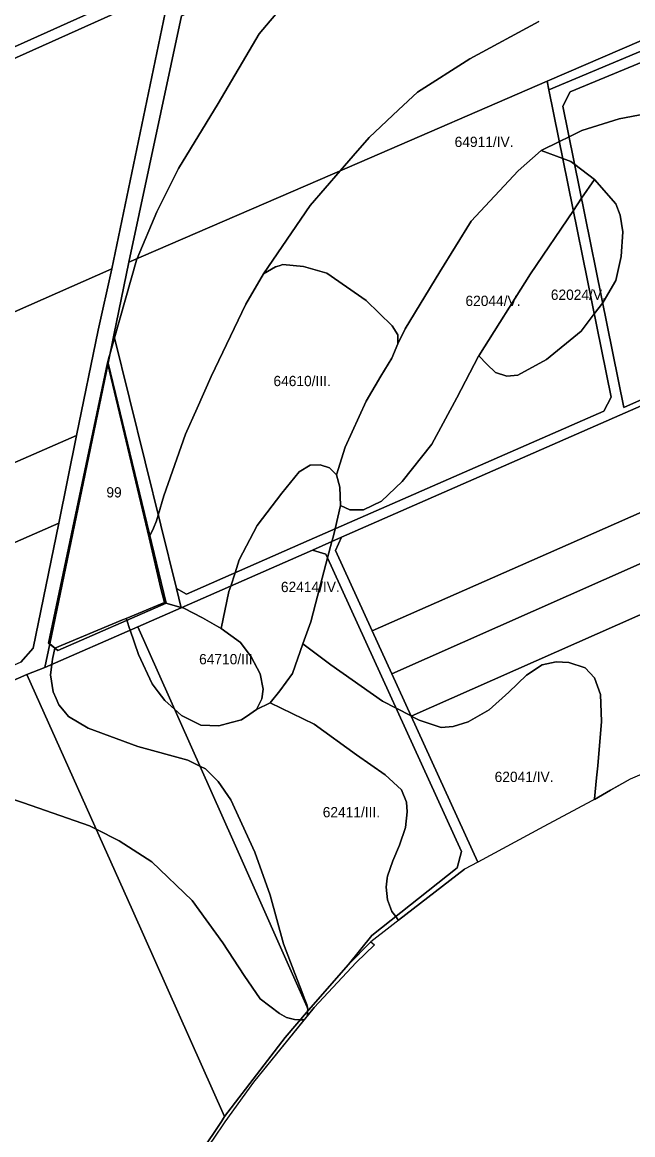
# Model space of a CAD drawing. Extents: x -522079 to -518833, y -1142400 to -1139961.
# Drawn here: x -520891 to -520594, y -1142050 to -1141508 of the extents above; entities that cross this region are included whole.
import ezdxf

# ---------------------------------------------------------------- set-up
doc = ezdxf.new("R2010")
doc.units = 0
for name, color, linetype in [('95560013', 7, 'Continuous'), ('95620013', 7, 'Continuous'), ('95640013', 7, 'Continuous'), ('95660013', 7, 'Continuous')]:
    doc.layers.add(name, color=color, linetype=linetype)

msp = doc.modelspace()

# ---------------------------------------------------------------- linework, layer by layer
at = {"layer": '95560013'}
for points in [[(-520659.49, -1141438.15), (-520585.72, -1141406.64), (-520580.93, -1141457.51), (-520574.39, -1141497.17), (-520572, -1141509.22), (-520635.55, -1141536.73), (-520726.9, -1141576.27), (-520838.97, -1141624.77), (-520813.35, -1141504.9)], [(-520821.3, -1141482.16), (-520824.28, -1141488.21), (-520974.97, -1141555.99), (-521072.78, -1141598.79), (-521078.78, -1141596.05), (-521084.21, -1141576.91), (-520955.18, -1141519.6), (-520826.14, -1141462.3)], [(-520819.82, -1141495.44), (-520822.47, -1141493.04), (-520972.97, -1141560.63), (-521070.28, -1141603.2), (-521076.03, -1141605.72), (-521077.42, -1141600.82), (-521072.78, -1141598.79), (-520974.97, -1141555.99), (-520824.28, -1141488.21), (-520821.3, -1141482.16)], [(-520822.47, -1141493.04), (-520819.82, -1141495.44), (-520847.36, -1141628.04), (-520954.68, -1141675.43), (-521044.98, -1141715.3), (-521058.67, -1141667), (-521074.66, -1141610.52), (-521070.28, -1141603.2), (-520972.97, -1141560.63)], [(-520572, -1141509.22), (-520571.03, -1141514.08), (-520634.69, -1141540.99), (-520635.55, -1141536.73)], [(-520624.36, -1141541.82), (-520627.91, -1141548.79), (-520598.21, -1141695.54), (-520529.1, -1141664.77), (-520528.04, -1141667.68), (-520597.66, -1141698.25), (-520735.52, -1141758.79), (-520749.7, -1141765.02), (-520813.61, -1141793.09), (-520815.91, -1141783.74), (-520811.05, -1141786.45), (-520751.28, -1141760.21), (-520608.03, -1141697.31), (-520604.47, -1141690.49), (-520634.69, -1141540.99), (-520571.03, -1141514.08), (-520569.98, -1141519.36)], [(-520627.91, -1141548.79), (-520624.36, -1141541.82), (-520569.98, -1141519.36), (-520566.58, -1141536.47), (-520557.06, -1141576.08), (-520545.85, -1141614.67), (-520536.49, -1141644.52), (-520529.1, -1141664.77), (-520598.21, -1141695.54)], [(-520608.03, -1141697.31), (-520751.28, -1141760.21), (-520811.05, -1141786.45), (-520815.91, -1141783.74), (-520846.32, -1141660.34), (-520838.97, -1141624.77), (-520726.9, -1141576.27), (-520635.55, -1141536.73), (-520634.69, -1141540.99), (-520604.47, -1141690.49)], [(-521044.98, -1141715.3), (-520954.68, -1141675.43), (-520847.36, -1141628.04), (-520854, -1141657.98), (-520864.49, -1141709.14), (-521026.62, -1141780.12)], [(-520738.58, -1141765.16), (-520735.52, -1141758.79), (-520597.66, -1141698.25), (-520528.04, -1141667.68), (-520522.71, -1141682.28), (-520510.4, -1141711.55), (-520625.27, -1141762.24), (-520720.69, -1141804.35)], [(-521026.62, -1141780.12), (-520864.49, -1141709.14), (-520873.01, -1141751.95), (-521016.76, -1141814.92)], [(-520501.37, -1141732.13), (-520539.21, -1141748.91), (-520711.18, -1141825.18), (-520720.69, -1141804.35), (-520625.27, -1141762.24), (-520510.4, -1141711.55), (-520506.95, -1141719.75)], [(-520711.18, -1141825.18), (-520539.21, -1141748.91), (-520501.37, -1141732.13), (-520491.98, -1141752.99), (-520530.72, -1141770.15), (-520701.74, -1141845.88)], [(-520873.01, -1141751.95), (-520885.53, -1141812.75), (-520891.63, -1141819.53), (-520930.02, -1141836.55), (-520997.06, -1141866.15), (-521003.04, -1141863.38), (-521016.76, -1141814.92)], [(-520701.74, -1141845.88), (-520530.72, -1141770.15), (-520491.98, -1141752.99), (-520490.19, -1141756.96), (-520458.87, -1141815.72), (-520465.55, -1141819.35), (-520477.66, -1141826.82), (-520503.7, -1141838.29), (-520515.18, -1141841.56), (-520545.58, -1141853.73), (-520565.76, -1141863.93), (-520595.23, -1141876.48), (-520613.84, -1141887.11), (-520637.23, -1141899.54), (-520669.31, -1141916.94)], [(-520720.87, -1141952.69), (-520679.41, -1141919.74), (-520677.16, -1141911.77), (-520743.17, -1141766.98), (-520749.7, -1141765.02), (-520735.52, -1141758.79), (-520738.58, -1141765.16), (-520720.69, -1141804.35), (-520711.18, -1141825.18), (-520701.74, -1141845.88), (-520669.31, -1141916.94), (-520675.72, -1141920.42), (-520721.33, -1141955.66), (-520732.26, -1141966.77)], [(-520788.5, -1141906.13), (-520834.71, -1141802.36), (-520813.61, -1141793.09), (-520749.7, -1141765.02), (-520743.17, -1141766.98), (-520677.16, -1141911.77), (-520679.41, -1141919.74), (-520720.87, -1141952.69), (-520732.26, -1141966.77), (-520751.6, -1141988.95)], [(-520837.29, -1141940.33), (-520888.63, -1141825.55), (-520879.93, -1141822.22), (-520834.71, -1141802.36), (-520788.5, -1141906.13), (-520751.6, -1141988.95), (-520762.92, -1142002.26), (-520792.44, -1142040.74)], [(-520997.93, -1141879.1), (-520995.39, -1141872.52), (-520888.63, -1141825.55), (-520837.29, -1141940.33), (-520792.44, -1142040.74), (-520794.02, -1142043.2), (-520832.63, -1142100.89), (-520865.14, -1142158.06), (-520874.16, -1142159.29), (-520905.36, -1142088.65), (-520939.85, -1142010.61), (-520967.25, -1141948.55)], [(-520865.14, -1142158.06), (-520832.63, -1142100.89), (-520794.02, -1142043.2), (-520792.44, -1142040.74), (-520762.92, -1142002.26), (-520751.6, -1141988.95), (-520732.26, -1141966.77), (-520721.33, -1141955.66), (-520719.53, -1141957.2), (-520728.5, -1141965.87), (-520748.85, -1141987.64), (-520778.35, -1142023.99), (-520792.36, -1142043.35), (-520798.04, -1142051.82), (-520812.28, -1142071.49), (-520845.48, -1142126.69), (-520864.2, -1142161.29), (-520868.95, -1142171.08), (-520870.13, -1142168.42)]]:
    msp.add_lwpolyline(points, close=True, dxfattribs=at)
at = {"layer": '95620013'}
msp.add_lwpolyline([(-520873.57, -1141813.91), (-520877.47, -1141810.66), (-520849.15, -1141674.02), (-520820.88, -1141790.77)], close=True, dxfattribs=at)
at = {"layer": '95640013'}
for points in [[(-520891.63, -1141819.53), (-520885.53, -1141812.75), (-520873.01, -1141751.95), (-520864.49, -1141709.14), (-520854, -1141657.98), (-520847.36, -1141628.04), (-520819.82, -1141495.44)], [(-520813.35, -1141504.9), (-520838.97, -1141624.77), (-520846.32, -1141660.34), (-520849.15, -1141674.02), (-520877.47, -1141810.66), (-520879.93, -1141822.22), (-520888.63, -1141825.55), (-520995.39, -1141872.52)]]:
    msp.add_lwpolyline(points, dxfattribs=at)
msp.add_lwpolyline([(-520879.93, -1141822.22), (-520877.47, -1141810.66), (-520873.57, -1141813.91), (-520820.88, -1141790.77), (-520849.15, -1141674.02), (-520846.32, -1141660.34), (-520815.91, -1141783.74), (-520813.61, -1141793.09), (-520834.71, -1141802.36)], close=True, dxfattribs=at)
at = {"layer": '95660013'}
for points in [[(-520750.59, -1141483.71), (-520775.72, -1141513.61), (-520795.59, -1141547.61), (-520814.88, -1141579.27), (-520825.4, -1141600.38), (-520835, -1141623.05), (-520835.33, -1141623.83), (-520845.99, -1141661.68), (-520848.28, -1141669.83), (-520848.56, -1141670.81), (-520849.41, -1141673.83), (-520855.9, -1141704.65), (-520878.15, -1141810.37), (-520877.51, -1141810.87), (-520875.07, -1141812.78), (-520876.18, -1141818.14), (-520876.52, -1141820.72), (-520877.18, -1141825.76), (-520875.88, -1141834.07), (-520874.41, -1141837.31), (-520873.04, -1141840.31), (-520870.45, -1141843.48), (-520868.37, -1141846.02), (-520858.79, -1141851.74), (-520834.71, -1141860.57), (-520810.38, -1141867.32), (-520804.51, -1141870.17), (-520801.83, -1141871.48), (-520795.62, -1141877.71), (-520789.4, -1141886.54), (-520777.75, -1141912), (-520770.24, -1141933.03), (-520763.77, -1141956.67), (-520758.33, -1141971.09), (-520755.76, -1141977.73), (-520753.41, -1141983.82), (-520752.49, -1141986.23), (-520752.2, -1141987.59), (-520752.11, -1141988.02), (-520752.02, -1141988.48), (-520752.06, -1141989.49), (-520752.11, -1141990.67), (-520752.18, -1141991.09), (-520752.32, -1141991.91), (-520748.85, -1141987.64), (-520753.57, -1141993.46), (-520753.61, -1141993.46), (-520754.4, -1141993.68), (-520755.69, -1141993.75), (-520756.06, -1141993.77), (-520758.4, -1141993.63), (-520762.35, -1141992.53), (-520765.71, -1141990.7), (-520775.16, -1141983.42), (-520783.02, -1141972.09), (-520793.28, -1141956.23), (-520808.24, -1141935.65), (-520827.9, -1141916.78), (-520843.72, -1141906.49), (-520854.94, -1141900.86), (-520858.25, -1141899.2), (-520890.31, -1141888.05), (-520908.69, -1141882.05)], [(-520639.54, -1141507.59), (-520673.15, -1141525.85), (-520698.71, -1141542.01), (-520707.92, -1141550.71), (-520722.16, -1141564.14), (-520729.88, -1141573.01), (-520736.22, -1141580.3), (-520750.87, -1141597.15), (-520773.5, -1141630.48), (-520782.08, -1141645.2), (-520798.97, -1141680.49), (-520805.8, -1141695.86), (-520811.44, -1141708.54), (-520821.96, -1141738.55), (-520824.73, -1141747.95), (-520825.56, -1141750.77), (-520827.11, -1141754.27), (-520828.8, -1141758.07), (-520829.23, -1141759.04), (-520846.04, -1141688.06), (-520849.25, -1141674.51), (-520849.41, -1141673.83), (-520848.56, -1141670.81), (-520848.28, -1141669.83), (-520845.99, -1141661.68), (-520835.33, -1141623.83), (-520835, -1141623.05), (-520825.4, -1141600.38), (-520814.88, -1141579.27), (-520795.59, -1141547.61), (-520775.72, -1141513.61), (-520750.59, -1141483.71)], [(-520580.87, -1141551.24), (-520600.51, -1141555.1), (-520618.75, -1141560.77), (-520624.88, -1141563.78), (-520629.61, -1141566.1), (-520638.49, -1141570.46), (-520649.69, -1141580.29), (-520672.45, -1141604.88), (-520687.85, -1141629.46), (-520704.66, -1141657.21), (-520708.14, -1141664.65), (-520708.14, -1141660.2), (-520710.91, -1141655.76), (-520723.65, -1141643.53), (-520742.76, -1141630.2), (-520754.11, -1141626.86), (-520764.08, -1141626.03), (-520765.88, -1141626.59), (-520767.68, -1141627.15), (-520773.5, -1141630.48), (-520750.87, -1141597.15), (-520736.22, -1141580.3), (-520729.88, -1141573.01), (-520722.16, -1141564.14), (-520707.92, -1141550.71), (-520698.71, -1141542.01), (-520673.15, -1141525.85), (-520639.54, -1141507.59)], [(-520575.63, -1141868.13), (-520595.23, -1141876.48), (-520604.76, -1141881.92), (-520604.78, -1141881.93), (-520612.62, -1141886.41), (-520612.59, -1141886.11), (-520611.53, -1141875.85), (-520610.93, -1141870.12), (-520609.06, -1141848.41), (-520609.6, -1141835.27), (-520612.54, -1141827.23), (-520617.08, -1141822.4), (-520625.1, -1141819.72), (-520631.25, -1141819.45), (-520637.93, -1141820.79), (-520645.68, -1141825.88), (-520654.23, -1141834.19), (-520663.85, -1141842.77), (-520674, -1141848.67), (-520681.22, -1141850.82), (-520687.1, -1141851.35), (-520697.79, -1141847.87), (-520701.65, -1141845.84), (-520701.79, -1141845.77), (-520708.96, -1141842.01), (-520715.69, -1141838.49), (-520740.81, -1141820.79), (-520754.42, -1141810.57), (-520750.56, -1141799.92), (-520745.01, -1141778.63), (-520742.37, -1141768.74), (-520740.27, -1141760.87), (-520739.71, -1141758.79), (-520738.75, -1141754.71), (-520736.09, -1141743.3), (-520731.62, -1141745.36), (-520724.96, -1141745.36), (-520716.21, -1141741.15), (-520706.06, -1141731.67), (-520691.7, -1141713.41), (-520679.45, -1141690.93), (-520668.95, -1141670.56), (-520668.84, -1141670.38), (-520664.91, -1141674.55), (-520660.67, -1141678.59), (-520655.16, -1141680.29), (-520649.86, -1141679.87), (-520635.86, -1141672.21), (-520619.1, -1141658.38), (-520612.65, -1141650.01), (-520608.51, -1141644.63), (-520608.29, -1141644.34), (-520602.14, -1141633.7), (-520599.59, -1141622), (-520598.74, -1141610.09), (-520600.02, -1141602), (-520602.14, -1141596.47), (-520612.58, -1141584.51), (-520622.15, -1141577.23), (-520624.13, -1141575.73), (-520627.95, -1141574.33), (-520638.49, -1141570.46), (-520629.61, -1141566.1), (-520624.88, -1141563.78), (-520618.75, -1141560.77), (-520600.51, -1141555.1), (-520580.87, -1141551.24)], [(-520908.69, -1141882.05), (-520890.31, -1141888.05), (-520858.25, -1141899.2), (-520854.94, -1141900.86), (-520843.72, -1141906.49), (-520827.9, -1141916.78), (-520808.24, -1141935.65), (-520793.28, -1141956.23), (-520783.02, -1141972.09), (-520775.16, -1141983.42), (-520765.71, -1141990.7), (-520762.35, -1141992.53), (-520758.4, -1141993.63), (-520756.06, -1141993.77), (-520755.69, -1141993.75), (-520754.4, -1141993.68), (-520753.61, -1141993.46), (-520753.57, -1141993.46), (-520778.35, -1142023.99), (-520792.36, -1142043.35), (-520798.04, -1142051.82)]]:
    msp.add_lwpolyline(points, dxfattribs=at)
for points in [[(-520612.58, -1141584.51), (-520618.82, -1141593.72), (-520622.83, -1141599.65), (-520643.74, -1141630.52), (-520668.84, -1141670.38), (-520668.95, -1141670.56), (-520679.45, -1141690.93), (-520691.7, -1141713.41), (-520706.06, -1141731.67), (-520716.21, -1141741.15), (-520724.96, -1141745.36), (-520731.62, -1141745.36), (-520736.09, -1141743.3), (-520736.33, -1141734.35), (-520738.02, -1141728.3), (-520733.89, -1141714.93), (-520723.65, -1141692.43), (-520716.42, -1141680.35), (-520711.18, -1141671.59), (-520708.14, -1141664.65), (-520704.66, -1141657.21), (-520687.85, -1141629.46), (-520672.45, -1141604.88), (-520649.69, -1141580.29), (-520638.49, -1141570.46), (-520627.95, -1141574.33), (-520624.13, -1141575.73), (-520622.15, -1141577.23)], [(-520649.86, -1141679.87), (-520655.16, -1141680.29), (-520660.67, -1141678.59), (-520664.91, -1141674.55), (-520668.84, -1141670.38), (-520643.74, -1141630.52), (-520622.83, -1141599.65), (-520618.82, -1141593.72), (-520612.58, -1141584.51), (-520602.14, -1141596.47), (-520600.02, -1141602), (-520598.74, -1141610.09), (-520599.59, -1141622), (-520602.14, -1141633.7), (-520608.29, -1141644.34), (-520608.51, -1141644.63), (-520612.65, -1141650.01), (-520619.1, -1141658.38), (-520635.86, -1141672.21)], [(-520708.14, -1141664.65), (-520711.18, -1141671.59), (-520716.42, -1141680.35), (-520723.65, -1141692.43), (-520733.89, -1141714.93), (-520738.02, -1141728.3), (-520741.4, -1141724.91), (-520745.98, -1141723.46), (-520750.8, -1141723.7), (-520756.11, -1141726.85), (-520764.55, -1141737.25), (-520776.61, -1141752.98), (-520785.3, -1141769.68), (-520787.39, -1141776.06), (-520789.49, -1141782.5), (-520790.36, -1141785.16), (-520794.08, -1141803.21), (-520803.15, -1141797.96), (-520812.23, -1141793.34), (-520813.41, -1141793), (-520813.65, -1141792.93), (-520820.97, -1141790.81), (-520821.76, -1141790.58), (-520823.4, -1141783.67), (-520829.23, -1141759.04), (-520828.8, -1141758.07), (-520827.11, -1141754.27), (-520825.56, -1141750.77), (-520824.73, -1141747.95), (-520821.96, -1141738.55), (-520811.44, -1141708.54), (-520805.8, -1141695.86), (-520798.97, -1141680.49), (-520782.08, -1141645.2), (-520773.5, -1141630.48), (-520767.68, -1141627.15), (-520765.88, -1141626.59), (-520764.08, -1141626.03), (-520754.11, -1141626.86), (-520742.76, -1141630.2), (-520723.65, -1141643.53), (-520710.91, -1141655.76), (-520708.14, -1141660.2)], [(-520874.97, -1141812.74), (-520875.07, -1141812.78), (-520877.51, -1141810.87), (-520878.15, -1141810.37), (-520855.9, -1141704.65), (-520849.41, -1141673.83), (-520849.25, -1141674.51), (-520846.04, -1141688.06), (-520829.23, -1141759.04), (-520823.4, -1141783.67), (-520821.76, -1141790.58), (-520840.33, -1141798.31), (-520842.08, -1141799.04)], [(-520770.34, -1141839.36), (-520776.96, -1141842.69), (-520774.4, -1141837.44), (-520773.64, -1141832.7), (-520775.17, -1141825.26), (-520779.51, -1141816.93), (-520784.75, -1141810.01), (-520794.08, -1141803.21), (-520790.36, -1141785.16), (-520789.49, -1141782.5), (-520787.39, -1141776.06), (-520785.3, -1141769.68), (-520776.61, -1141752.98), (-520764.55, -1141737.25), (-520756.11, -1141726.85), (-520750.8, -1141723.7), (-520745.98, -1141723.46), (-520741.4, -1141724.91), (-520738.02, -1141728.3), (-520736.33, -1141734.35), (-520736.09, -1141743.3), (-520738.75, -1141754.71), (-520739.71, -1141758.79), (-520740.27, -1141760.87), (-520742.37, -1141768.74), (-520745.01, -1141778.63), (-520750.56, -1141799.92), (-520754.42, -1141810.57), (-520759.49, -1141825.09), (-520765.52, -1141833.56)], [(-520794.08, -1141803.21), (-520784.75, -1141810.01), (-520779.51, -1141816.93), (-520775.17, -1141825.26), (-520773.64, -1141832.7), (-520774.4, -1141837.44), (-520776.96, -1141842.69), (-520780.19, -1141844.86), (-520784.24, -1141847.57), (-520789.34, -1141848.99), (-520795.23, -1141850.64), (-520804.05, -1141850.26), (-520806.58, -1141848.97), (-520813.38, -1141845.51), (-520816.89, -1141842.38), (-520821.56, -1141838.21), (-520824.7, -1141834.06), (-520827.69, -1141830.13), (-520834.33, -1141815.91), (-520838.4, -1141803.98), (-520838.5, -1141803.7), (-520840.04, -1141799.18), (-520840.17, -1141798.78), (-520840.33, -1141798.31), (-520821.76, -1141790.58), (-520820.97, -1141790.81), (-520813.65, -1141792.93), (-520813.41, -1141793), (-520812.23, -1141793.34), (-520803.15, -1141797.96)], [(-520707.86, -1141945.25), (-520675.72, -1141920.42), (-520721.33, -1141955.66), (-520719.53, -1141957.2), (-520728.5, -1141965.87), (-520748.85, -1141987.64), (-520752.32, -1141991.91), (-520752.18, -1141991.09), (-520752.11, -1141990.67), (-520752.06, -1141989.49), (-520752.02, -1141988.48), (-520752.11, -1141988.02), (-520752.2, -1141987.59), (-520752.49, -1141986.23), (-520753.41, -1141983.82), (-520755.76, -1141977.73), (-520758.33, -1141971.09), (-520763.77, -1141956.67), (-520770.24, -1141933.03), (-520777.75, -1141912), (-520789.4, -1141886.54), (-520795.62, -1141877.71), (-520801.83, -1141871.48), (-520804.51, -1141870.17), (-520810.38, -1141867.32), (-520834.71, -1141860.57), (-520858.79, -1141851.74), (-520868.37, -1141846.02), (-520870.45, -1141843.48), (-520873.04, -1141840.31), (-520874.41, -1141837.31), (-520875.88, -1141834.07), (-520877.18, -1141825.76), (-520876.52, -1141820.72), (-520876.18, -1141818.14), (-520875.07, -1141812.78), (-520874.97, -1141812.74), (-520842.08, -1141799.04), (-520840.33, -1141798.31), (-520840.17, -1141798.78), (-520840.04, -1141799.18), (-520838.5, -1141803.7), (-520838.4, -1141803.98), (-520834.33, -1141815.91), (-520827.69, -1141830.13), (-520824.7, -1141834.06), (-520821.56, -1141838.21), (-520816.89, -1141842.38), (-520813.38, -1141845.51), (-520806.58, -1141848.97), (-520804.05, -1141850.26), (-520795.23, -1141850.64), (-520789.34, -1141848.99), (-520784.24, -1141847.57), (-520780.19, -1141844.86), (-520776.96, -1141842.69), (-520770.34, -1141839.36), (-520748.83, -1141849.75), (-520728.25, -1141864.76), (-520714.36, -1141874.41), (-520706.34, -1141881.65), (-520703.93, -1141887.81), (-520703.67, -1141892.37), (-520704.47, -1141900.14), (-520707.41, -1141908.72), (-520710.62, -1141916.23), (-520713.29, -1141923.74), (-520713.39, -1141924.73), (-520713.82, -1141929.1), (-520713.29, -1141935.26), (-520711.78, -1141939.24), (-520711.15, -1141940.89), (-520709.23, -1141943.44), (-520708.14, -1141944.88)], [(-520613.84, -1141887.11), (-520637.23, -1141899.54), (-520669.31, -1141916.94), (-520675.72, -1141920.42), (-520707.86, -1141945.25), (-520708.14, -1141944.88), (-520709.23, -1141943.44), (-520711.15, -1141940.89), (-520711.78, -1141939.24), (-520713.29, -1141935.26), (-520713.82, -1141929.1), (-520713.39, -1141924.73), (-520713.29, -1141923.74), (-520710.62, -1141916.23), (-520707.41, -1141908.72), (-520704.47, -1141900.14), (-520703.67, -1141892.37), (-520703.93, -1141887.81), (-520706.34, -1141881.65), (-520714.36, -1141874.41), (-520728.25, -1141864.76), (-520748.83, -1141849.75), (-520770.34, -1141839.36), (-520765.52, -1141833.56), (-520759.49, -1141825.09), (-520754.42, -1141810.57), (-520740.81, -1141820.79), (-520715.69, -1141838.49), (-520708.96, -1141842.01), (-520701.79, -1141845.77), (-520701.65, -1141845.84), (-520697.79, -1141847.87), (-520687.1, -1141851.35), (-520681.22, -1141850.82), (-520674, -1141848.67), (-520663.85, -1141842.77), (-520654.23, -1141834.19), (-520645.68, -1141825.88), (-520637.93, -1141820.79), (-520631.25, -1141819.45), (-520625.1, -1141819.72), (-520617.08, -1141822.4), (-520612.54, -1141827.23), (-520609.6, -1141835.27), (-520609.06, -1141848.41), (-520610.93, -1141870.12), (-520611.53, -1141875.85), (-520612.59, -1141886.11), (-520612.62, -1141886.41), (-520604.78, -1141881.93), (-520604.76, -1141881.92)]]:
    msp.add_lwpolyline(points, close=True, dxfattribs=at)

# ---------------------------------------------------------------- texts
for s, rotation, p in [('64911/IV.', 0, (-520680.57, -1141568.74)), ('62044/V.', 360, (-520675.3, -1141646.15)), ('62024/V.', 0, (-520633.79, -1141643.17)), ('64610/III.', 360, (-520768.69, -1141685.18)), ('99', 360, (-520849.95, -1141739.37)), ('62414/IV.', 0, (-520765.08, -1141785.45)), ('64710/III.', 0, (-520804.86, -1141820.61)), ('62041/IV.', 360, (-520661.11, -1141877.91)), ('62411/III.', 0, (-520744.72, -1141895.11))]:
    msp.add_text(s, height=5, rotation=rotation, dxfattribs=at).set_placement(p)

doc.saveas('drawing.dxf')
